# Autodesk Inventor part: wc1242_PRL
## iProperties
Shininess: 64.0
Length Units: 11272
Angle Units: 11279
Time Units: 11290
Mass Units: 11286
Length Display Precision: 3
Angle Display Precision: 2
Compacted: True
Part Number: wc1242_PRL
Document SubType Name: Modeling
Created: 2004-08
Designer: John Blackburn
Manufacturer: Standard
Standards Organization: Custom
Material: Lexan, Clear
Density: 0.0
Volumn: 0.0
Area: 0.0
PropertySet Name: Model Information
Control State: 0
Master: False
Checked Out: False
Author: John Blackburn
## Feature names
1. Revolution1
